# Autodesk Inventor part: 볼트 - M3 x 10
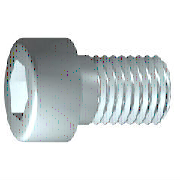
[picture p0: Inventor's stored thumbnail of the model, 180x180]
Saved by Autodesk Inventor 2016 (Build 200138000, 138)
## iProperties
Created: 2012-02
Part Number: 볼트 - M3 x 10
Material: 스테인리스강
Description: 6각 소켓 머리 캡 나사
Document SubType Name: Modeling
Standard: ISO 4762
Designer: mduedu
Standard Revision: Fourth edition 2004-03-01
Standards Organization: ISO
Language: ko-KR
Size Designation: M3 x 10
Categories: <MemberInstance><Categories><Category DisplayName="조임쇠" InternalName="e4da775c-781d-43d5-af7c-5136215cf5a6" Mnemonic="FSTN"><Category DisplayName="볼트" InternalN
Density: 8.08 g/cm^3
Mass: 1.0701 g
Surface Area: 2.01851 cm^2
Volume: 0.132438 cm^3
Appearance: 반광택
IsCustomPart: 0
Author: mduedu
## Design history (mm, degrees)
sketch "스케치1"
  geometry: L1 (-0.867, 0)-(10, 0); L2 (10, 0)-(10, 1.5); L3 (10, 1.5)-(1.25, 1.5); L4 (1.25, 1.5)-(0.943, 1.5); L5 (0.943, 1.5)-(0, 1.5); L6 (0, 1.5)-(0, 2.75); L7 (0, 2.75)-(-3, 2.75); L8 (-3, 2.75)-(-3, 1.443); L9 (-3, 1.443)-(-1.7, 1.443); L10 (-1.7, 1.443)-(-0.867, 0); L11 (-5.6, 0)-(12.6, 0) reference; L12 (0, -0.55)-(0, 3.3) reference; L13 (1.25, 1.5)-(0, 1.5)
  constraints: 22 end point, 6 parallel, 2 collinear, 2 perpendicular, 1 horizontal, 1 point on line
  dimensions: "d1" = 8.75 distance from line of L3.end L2 (= GEL); "d2" = 0.30683 distance of L4.end L3.end (computed from GAL); "d3" = 3 distance between parallel lines of L8 L6 (= KOH); "d4" = 1.3 distance of L8.end L9.end (= INTI); "d5" = 60 deg angle of L10 L1; "d6" = 3 diameter of L3 L1 (= GD); "d7" = 3 diameter of L5 L1 (= BDM); "d8" = 2.88675 diameter of L9 L1 (= 1.1547 x SW); "d9" = 5.5 diameter of L7 L1 (= KOD); "d26" = 10 distance between parallel lines of L12 L2 (= NLG)
revolve "본체" sketch "스케치1" stored, may be unused: angle "d10" = 90 deg
sketch "스케치2"
  geometry: L1 (0, -3.85)-(0, 3.85) reference; L2 (-3.85, 0)-(3.85, 0) reference; L3 (1.443, 0)-(0.722, -1.25); L4 (0.722, -1.25)-(-0.722, -1.25); L5 (-0.722, -1.25)-(-1.443, 0); L6 (-1.443, 0)-(-0.722, 1.25); L7 (-0.722, 1.25)-(0.722, 1.25); L8 (0.722, 1.25)-(1.443, 0); 2 further points
  constraints: 12 end point, 1 coincident, 1 horizontal alignment, 1 point on line, 12 other
extrude "슬롯" join sketch "스케치2" stored distance "d11" = 10; taper "d12" = 0 deg
workplane "Work Plane1"
fillet "Fillet2" dims "d30" = 0.1 (= R)
body "Solid1"
fillet "모깎기1" dims "d17" = 0.3 (= RR)
feature "스레드" dims "d13" = 8.75 (= GEL), "d14" = 0
chamfer "모따기1" distance "d15" = 0.30673 (= -0.5 x SPD + 0.5 x GD); stored, may be unused: second distance "d16" = 0.30673 (= GUL), angle "d27" = 45 deg
other parameters: "GD" = 3 [user parameter; used in 2 equation terms], "NLG" = 10 [user parameter; used in 1 equation term], "GEL" = 8.75 [user parameter; used in 2 equation terms], "KOD" = 5.5 [user parameter; used in 1 equation term], "KOH" = 3 [user parameter; used in 1 equation term], "INTI" = 1.3 [user parameter; used in 1 equation term], "GAL" = 0.30673 (= 0.61345 x PTC) [user parameter; used in 1 equation term], "GUL" = 0.30673 (= 0.61345 x PTC) [user parameter; used in 1 equation term], "BDM" = 3 (= NND) [user parameter; used in 1 equation term], "SW" = 2.5 [user parameter; used in 2 equation terms], "RR" = 0.3 [user parameter; used in 1 equation term], "SPD" = 2.38655 (= NND - 1.2269 x PTC) [user parameter; used in 1 equation term], "d19" = 0, "d28" = 0, "d29" = 0, "R" = 0.1 [user parameter; used in 1 equation term], "TOA" = 30 deg [user parameter], "GD1" = 2.38655 (= THREADDIA - 1.2269 x PTC) [user parameter], "THREADDIA" = 3 [user parameter; used in 1 equation term], "FAWI" = 45 deg [user parameter], "PTC" = 0.5 [user parameter; used in 5 equation terms], "NND" = 3 [user parameter; used in 2 equation terms], "E0" = 2.8875 (= 1.155 x SW) [user parameter]
